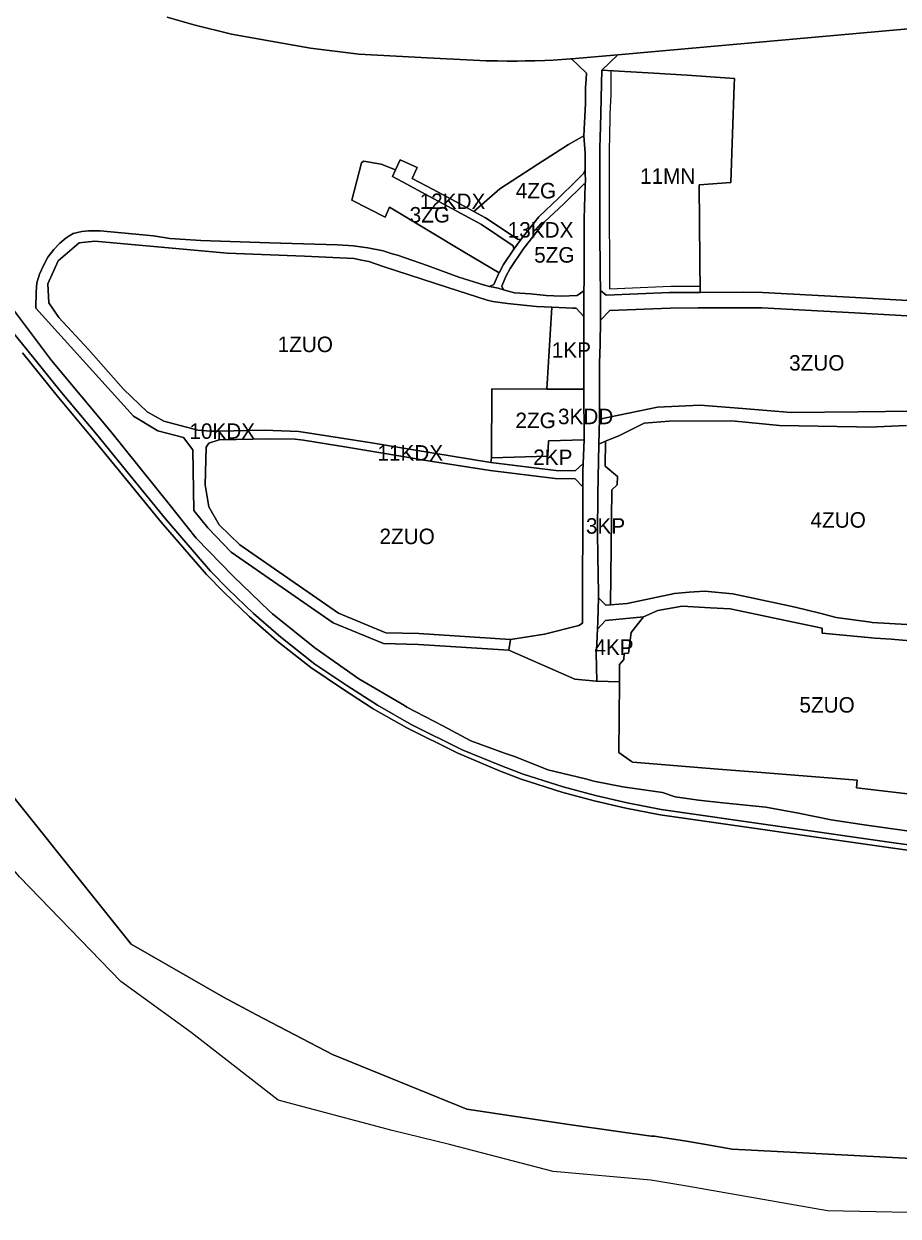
# Model space of a CAD drawing. Extents: x 7417411 to 7420955, y 5545251 to 5546537.
# Drawn here: x 7419574 to 7420138, y 5545252 to 5546021 of the extents above; entities that cross this region are included whole.
import ezdxf

# ---------------------------------------------------------------- set-up
doc = ezdxf.new("R2010")
doc.units = 0
for name, color, linetype in [('linie_rozgraniczajace', 7, 'Continuous'), ('linie_zabudowy_nieprzekraczalne', 7, 'Continuous'), ('oznaczenia_przeznaczen', 7, 'Continuous')]:
    doc.layers.add(name, color=color, linetype=linetype)

msp = doc.modelspace()

# ---------------------------------------------------------------- linework, layer by layer
at = {"layer": 'linie_rozgraniczajace'}
for points in [[(7419666.58, 5546025.71), (7419683.77, 5546020.6), (7419708.1, 5546014.69), (7419737.03, 5546009.53), (7419759.01, 5546005.6), (7419790.17, 5546001.84), (7419838.21, 5545999.23), (7419859.82, 5545998.12), (7419872.15, 5545997.57), (7419879.58, 5545997.4), (7419885.84, 5545997.33), (7419892.16, 5545997.32), (7419897.44, 5545997.4), (7419903.7, 5545997.53), (7419910.02, 5545997.76), (7419915.33, 5545998), (7419926.8, 5545998.72), (7419927.2, 5545998.75), (7419936.91, 5545989.53), (7419936.79, 5545985.72), (7419936.26, 5545979.98), (7419936.37, 5545970.02), (7419935.1, 5545949.12), (7419925.35, 5545943.45), (7419905.52, 5545930.91), (7419881.13, 5545914.93), (7419864.34, 5545900.22), (7419855.19, 5545905.19), (7419838.11, 5545914.37), (7419824.53, 5545921.65), (7419827.75, 5545928.74), (7419816.82, 5545933.69), (7419813.84, 5545927.12), (7419804.61, 5545930.73), (7419793.07, 5545932.68), (7419791.82, 5545931.67), (7419785.61, 5545907.57), (7419807.11, 5545896.72), (7419809.91, 5545903.04), (7419858.39, 5545873.92), (7419880.63, 5545860.7), (7419880.49, 5545860.43), (7419877.23, 5545853.15), (7419874.48, 5545851.98), (7419871.2, 5545852.8), (7419854.66, 5545857.97), (7419834.23, 5545865.36), (7419815.01, 5545872.14), (7419811.57, 5545872.89), (7419805.72, 5545874.8), (7419795.94, 5545876.75), (7419786.42, 5545878.09), (7419783.39, 5545878.32), (7419779.83, 5545878.59), (7419779.8, 5545878.59), (7419776.33, 5545878.67), (7419732.46, 5545880.14), (7419688.18, 5545881.56), (7419678.3, 5545882.15), (7419668.31, 5545882.92), (7419657.8, 5545884.64), (7419623.35, 5545887.75), (7419615.89, 5545887.87), (7419611.45, 5545887.4), (7419605.98, 5545886.05), (7419601.5, 5545883.34), (7419597.32, 5545879.85), (7419593.57, 5545875.79), (7419589.68, 5545870.81), (7419586.71, 5545865.38), (7419584.22, 5545859.91)], [(7420168.36, 5546020.35), (7419957.04, 5546001.38), (7419927.2, 5545998.75), (7419926.8, 5545998.72), (7419915.33, 5545998), (7419910.02, 5545997.76), (7419903.7, 5545997.53), (7419897.44, 5545997.4), (7419892.16, 5545997.32), (7419885.84, 5545997.33), (7419879.58, 5545997.4), (7419872.15, 5545997.57), (7419859.82, 5545998.12), (7419838.21, 5545999.23), (7419790.17, 5546001.84), (7419759.01, 5546005.6), (7419737.03, 5546009.53), (7419708.1, 5546014.69), (7419683.77, 5546020.6), (7419666.58, 5546025.71)], [(7420170.21, 5545841.46), (7420110.4, 5545844.83), (7420050.33, 5545848.06), (7420038.05, 5545848.19), (7420010.26, 5545848.07), (7420010.05, 5545868.95), (7420009.56, 5545917.41), (7420029.96, 5545919), (7420032.09, 5545981.78), (7420032.44, 5545986.18), (7420001.78, 5545988.13), (7419980.39, 5545989.43), (7419946.91, 5545991.52), (7419957.04, 5546001.38), (7420168.36, 5546020.35)], [(7420258.68, 5545252.15), (7420092.31, 5545255.64), (7420001.57, 5545271.49), (7419978.39, 5545275.32), (7419915.42, 5545281.02), (7419848.54, 5545298.42), (7419811.72, 5545307.45), (7419738.09, 5545326.91), (7419682.01, 5545370.56), (7419636.59, 5545403.58), (7419571.38, 5545471.15), (7419500.52, 5545553.16), (7419453.87, 5545603.37), (7419413.65, 5545646.88), (7419376.29, 5545683.4), (7419343.05, 5545716.25), (7419290.63, 5545776.17), (7419284.76, 5545784.57), (7419241.76, 5545833.26), (7419228.74, 5545841.09), (7419194.92, 5545858.79), (7419126.7, 5545886.6)], [(7420221.87, 5545481.1), (7420135.05, 5545493), (7419984.97, 5545514.41), (7419963.09, 5545518.7), (7419942.7, 5545523.52), (7419921.96, 5545529.13), (7419895.98, 5545537.26), (7419882.21, 5545542.72), (7419856.77, 5545552.95), (7419823.8, 5545569.35), (7419802.15, 5545581.76), (7419782.33, 5545594.48), (7419761.8, 5545608.35), (7419739.86, 5545625.61), (7419722.31, 5545640.96), (7419705.74, 5545656.93), (7419694.59, 5545668.32), (7419665.42, 5545702.07), (7419642.4, 5545730.26), (7419620.94, 5545756.55), (7419598.34, 5545783.6), (7419576.04, 5545811.27), (7419539.44, 5545856.07)], [(7419539.44, 5545856.07), (7419576.04, 5545811.27), (7419598.34, 5545783.6), (7419620.94, 5545756.55), (7419642.4, 5545730.26), (7419665.42, 5545702.07), (7419694.59, 5545668.32), (7419705.74, 5545656.93), (7419722.31, 5545640.96), (7419739.86, 5545625.61), (7419761.8, 5545608.35), (7419782.33, 5545594.48), (7419802.15, 5545581.76), (7419823.8, 5545569.35), (7419856.77, 5545552.95), (7419882.21, 5545542.72), (7419895.98, 5545537.26), (7419921.96, 5545529.13), (7419942.7, 5545523.52), (7419963.09, 5545518.7), (7419984.97, 5545514.41), (7420135.05, 5545493), (7420221.87, 5545481.1)], [(7419584.22, 5545859.91), (7419582.46, 5545854.21), (7419581.99, 5545848.36), (7419581.95, 5545837.84), (7419644.89, 5545768.14), (7419660.52, 5545758.68), (7419677.18, 5545754.39), (7419683.03, 5545746.6), (7419683.71, 5545707.48), (7419692.66, 5545696.13), (7419707.87, 5545680.56), (7419773.59, 5545634.93), (7419806.13, 5545621.55), (7419828.59, 5545621.01), (7419886.89, 5545617.18), (7419929.31, 5545598.57), (7419943.05, 5545597.24), (7419943.6, 5545597.22), (7419958.16, 5545596.85), (7419957.78, 5545551.25), (7419966.03, 5545545.48), (7419966.69, 5545545.02), (7420021.74, 5545540.53), (7420049.7, 5545538.31), (7420111.37, 5545533.38), (7420111.11, 5545528.55), (7420200.88, 5545517.97)], [(7420169.65, 5545831.47), (7420109.85, 5545834.85), (7420050.01, 5545838.06), (7420038.02, 5545838.19), (7420008.97, 5545838.06), (7419990.76, 5545837.98), (7419951.96, 5545836.4), (7419945.89, 5545830.16), (7419946.01, 5545839.64), (7419945.9, 5545849.36), (7419949.65, 5545846.32), (7419990.53, 5545847.98), (7420008.92, 5545848.06), (7420010.26, 5545848.07), (7420038.05, 5545848.19), (7420050.33, 5545848.06), (7420110.4, 5545844.83), (7420170.21, 5545841.46)], [(7420155.78, 5545499.11), (7420115.86, 5545504.53), (7420094.64, 5545507.9), (7420073.57, 5545512.14), (7420052.55, 5545516.03), (7420024.79, 5545518.7), (7420009.07, 5545520.48), (7419994.07, 5545522.71), (7419985.84, 5545525.56), (7419960.45, 5545529.08), (7419941.63, 5545532.71), (7419936.37, 5545534.17), (7419911.92, 5545540.05), (7419891.21, 5545548.51), (7419884.14, 5545550.77), (7419862.36, 5545558.84), (7419844.27, 5545568.42), (7419821.09, 5545580.55), (7419819.5, 5545581.6), (7419790.12, 5545598.73), (7419761.76, 5545618.85), (7419734.55, 5545640.69), (7419732.24, 5545642.7), (7419709.32, 5545664.77), (7419685.14, 5545689.52), (7419667.86, 5545711.44), (7419630.05, 5545758.49), (7419591.92, 5545804.1), (7419564.22, 5545841.04)], [(7419564.22, 5545841.04), (7419591.92, 5545804.1), (7419630.05, 5545758.49), (7419667.86, 5545711.44), (7419685.14, 5545689.52), (7419709.32, 5545664.77), (7419732.24, 5545642.7), (7419734.55, 5545640.69), (7419761.76, 5545618.85), (7419790.12, 5545598.73), (7419819.5, 5545581.6), (7419821.09, 5545580.55), (7419844.27, 5545568.42), (7419862.36, 5545558.84), (7419884.14, 5545550.77), (7419891.21, 5545548.51), (7419911.92, 5545540.05), (7419936.37, 5545534.17), (7419941.63, 5545532.71), (7419960.45, 5545529.08), (7419985.84, 5545525.56), (7419994.07, 5545522.71), (7420009.07, 5545520.48), (7420024.79, 5545518.7), (7420052.55, 5545516.03), (7420073.57, 5545512.14), (7420094.64, 5545507.9), (7420115.86, 5545504.53), (7420155.78, 5545499.11)], [(7420147.34, 5545771.5), (7420112.06, 5545771.08), (7420068.85, 5545770.57), (7420037.46, 5545773.21), (7420010.13, 5545775.34), (7419982.63, 5545774), (7419945.21, 5545766.35), (7419945.35, 5545776.95), (7419945.4, 5545802.63), (7419945.69, 5545814.38), (7419945.89, 5545830.16), (7419951.96, 5545836.4), (7419990.76, 5545837.98), (7420008.97, 5545838.06), (7420038.02, 5545838.19), (7420050.01, 5545838.06), (7420109.85, 5545834.85), (7420169.65, 5545831.47)], [(7419573.33, 5545809.06), (7419595.63, 5545781.39), (7419618.23, 5545754.34), (7419639.69, 5545728.05), (7419662.71, 5545699.86), (7419691.88, 5545666.11), (7419703.03, 5545654.71), (7419719.6, 5545638.74), (7419737.15, 5545623.39), (7419759.09, 5545606.14), (7419779.62, 5545592.26), (7419799.44, 5545579.54), (7419821.09, 5545567.13), (7419854.06, 5545550.73), (7419880.92, 5545539.46), (7419894.81, 5545533.96), (7419920.98, 5545525.77), (7419941.84, 5545520.13), (7419962.35, 5545515.28), (7419984.39, 5545510.96), (7420134.57, 5545489.53), (7420221.39, 5545477.63)], [(7420221.39, 5545477.63), (7420134.57, 5545489.53), (7419984.39, 5545510.96), (7419962.35, 5545515.28), (7419941.84, 5545520.13), (7419920.98, 5545525.77), (7419894.81, 5545533.96), (7419880.92, 5545539.46), (7419854.06, 5545550.73), (7419821.09, 5545567.13), (7419799.44, 5545579.54), (7419779.62, 5545592.26), (7419759.09, 5545606.14), (7419737.15, 5545623.39), (7419719.6, 5545638.74), (7419703.03, 5545654.71), (7419691.88, 5545666.11), (7419662.71, 5545699.86), (7419639.69, 5545728.05), (7419618.23, 5545754.34), (7419595.63, 5545781.39), (7419573.33, 5545809.06)], [(7420143.31, 5545762.32), (7420119.12, 5545761.17), (7420111.09, 5545761.33), (7420061.26, 5545762.26), (7420030.56, 5545765.15), (7419990.14, 5545765.11), (7419974.08, 5545763.67), (7419958.15, 5545755.85), (7419949.12, 5545752.01), (7419944.97, 5545750.25), (7419945.21, 5545766.35), (7419982.63, 5545774), (7420010.13, 5545775.34), (7420037.46, 5545773.21), (7420068.85, 5545770.57), (7420112.06, 5545771.08), (7420147.34, 5545771.5)], [(7420143.47, 5545633.81), (7420121.13, 5545635.19), (7420120.27, 5545635.24), (7420097.93, 5545638.44), (7420087.33, 5545641.07), (7420071.39, 5545645.03), (7420063.48, 5545646.75), (7420031.23, 5545653.68), (7420013, 5545655.38), (7420003.06, 5545654.63), (7419993.71, 5545653.93), (7419963.08, 5545647.49), (7419952.44, 5545646.62), (7419953.27, 5545720.72), (7419956.7, 5545724.02), (7419956.87, 5545729.28), (7419948.86, 5545736.06), (7419949.12, 5545752.01), (7419958.15, 5545755.85), (7419974.08, 5545763.67), (7419990.14, 5545765.11), (7420030.56, 5545765.15), (7420061.26, 5545762.26), (7420111.09, 5545761.33), (7420119.12, 5545761.17), (7420143.31, 5545762.32)], [(7420177.52, 5545620.45), (7420133.26, 5545624.46), (7420123.12, 5545624.99), (7420088.86, 5545628.15), (7420088.77, 5545631.5), (7420065.26, 5545636.42), (7420034.69, 5545642.83), (7420029.6, 5545643.89), (7420016.81, 5545644.6), (7420006, 5545645.2), (7419998.55, 5545645.61), (7419982.91, 5545642.83), (7419973.68, 5545638.72), (7419949.24, 5545636.39), (7419944.01, 5545630.93), (7419944.26, 5545635.91), (7419944.58, 5545650.98), (7419949.49, 5545646.39), (7419952.44, 5545646.62), (7419963.08, 5545647.49), (7419993.71, 5545653.93), (7420003.06, 5545654.63), (7420013, 5545655.38), (7420031.23, 5545653.68), (7420063.48, 5545646.75), (7420071.39, 5545645.03), (7420087.33, 5545641.07), (7420097.93, 5545638.44), (7420120.27, 5545635.24), (7420121.13, 5545635.19), (7420143.47, 5545633.81)], [(7420200.88, 5545517.97), (7420111.11, 5545528.55), (7420111.37, 5545533.38), (7420049.7, 5545538.31), (7420021.74, 5545540.53), (7419966.69, 5545545.02), (7419966.03, 5545545.48), (7419957.78, 5545551.25), (7419958.16, 5545596.85), (7419958.25, 5545607.99), (7419960.94, 5545611.36), (7419961.17, 5545615.23), (7419963.92, 5545615.35), (7419965.7, 5545628.78), (7419973.68, 5545638.72), (7419982.91, 5545642.83), (7419998.55, 5545645.61), (7420006, 5545645.2), (7420016.81, 5545644.6), (7420029.6, 5545643.89), (7420034.69, 5545642.83), (7420065.26, 5545636.42), (7420088.77, 5545631.5), (7420088.86, 5545628.15), (7420123.12, 5545624.99), (7420133.26, 5545624.46), (7420177.52, 5545620.45)], [(7419538.5, 5545558.64), (7419643.4, 5545427.59), (7419702.88, 5545393.38), (7419724.2, 5545382.02), (7419773.24, 5545356.42), (7419859.86, 5545321.2), (7419925.47, 5545311.24), (7419955.86, 5545306.93), (7419978.62, 5545303.7), (7419980.72, 5545303.76), (7419984.66, 5545303.08), (7419994.42, 5545301.67), (7420001.49, 5545300.57), (7420013.86, 5545298.41), (7420030.92, 5545295.44), (7420105.46, 5545291.6), (7420195.89, 5545286.82)], [(7420195.89, 5545286.82), (7420105.46, 5545291.6), (7420030.92, 5545295.44), (7420013.86, 5545298.41), (7420001.49, 5545300.57), (7419994.42, 5545301.67), (7419984.66, 5545303.08), (7419980.72, 5545303.76), (7419978.62, 5545303.7), (7419955.86, 5545306.93), (7419925.47, 5545311.24), (7419859.86, 5545321.2), (7419773.24, 5545356.42), (7419724.2, 5545382.02), (7419702.88, 5545393.38), (7419643.4, 5545427.59), (7419538.5, 5545558.64)]]:
    msp.add_lwpolyline(points, dxfattribs=at)
for points in [[(7419886.89, 5545617.18), (7419887.94, 5545624.12), (7419909.77, 5545627.62), (7419932.08, 5545633.13), (7419934.25, 5545634.77), (7419934.55, 5545722.65), (7419934.57, 5545727.64), (7419934.66, 5545732.8), (7419934.84, 5545737.8), (7419935.38, 5545752.92), (7419935.4, 5545753.62), (7419935.3, 5545785.56), (7419935.18, 5545832.57), (7419935.17, 5545837.55), (7419935.14, 5545849.17), (7419935.35, 5545855.31), (7419935.36, 5545861.5), (7419935.35, 5545869.11), (7419935.34, 5545895.47), (7419936.16, 5545917.56), (7419936.26, 5545920.25), (7419936.16, 5545925.11), (7419936.13, 5545927.16), (7419935.97, 5545937.91), (7419935.1, 5545949.12), (7419936.37, 5545970.02), (7419936.26, 5545979.98), (7419936.79, 5545985.72), (7419936.91, 5545989.53), (7419927.2, 5545998.75), (7419957.04, 5546001.38), (7419946.91, 5545991.52), (7419946.46, 5545973.54), (7419946.06, 5545963.03), (7419945.78, 5545947.73), (7419945.59, 5545941.76), (7419945.59, 5545914.41), (7419945.54, 5545888.51), (7419945.72, 5545861.23), (7419945.9, 5545849.36), (7419946.01, 5545839.64), (7419945.89, 5545830.16), (7419945.69, 5545814.38), (7419945.4, 5545802.63), (7419945.35, 5545776.95), (7419945.21, 5545766.35), (7419944.97, 5545750.25), (7419944.25, 5545717.73), (7419943.96, 5545692.69), (7419944.33, 5545678.08), (7419944.62, 5545653.83), (7419944.58, 5545650.98), (7419944.26, 5545635.91), (7419944.01, 5545630.93), (7419943.78, 5545626.45), (7419943.48, 5545620.76), (7419943.18, 5545615.27), (7419943.6, 5545597.22), (7419943.05, 5545597.24), (7419929.31, 5545598.57)], [(7419945.9, 5545849.36), (7419945.72, 5545861.23), (7419945.54, 5545888.51), (7419945.59, 5545914.41), (7419945.59, 5545941.76), (7419945.78, 5545947.73), (7419946.06, 5545963.03), (7419946.46, 5545973.54), (7419946.91, 5545991.52), (7419980.39, 5545989.43), (7420001.78, 5545988.13), (7420032.44, 5545986.18), (7420032.09, 5545981.78), (7420029.96, 5545919), (7420009.56, 5545917.41), (7420010.05, 5545868.95), (7420010.26, 5545848.07), (7420008.92, 5545848.06), (7419990.53, 5545847.98), (7419949.65, 5545846.32)], [(7419864.34, 5545900.22), (7419881.13, 5545914.93), (7419905.52, 5545930.91), (7419925.35, 5545943.45), (7419935.1, 5545949.12), (7419935.97, 5545937.91), (7419936.13, 5545927.16), (7419935.12, 5545924.91), (7419930.23, 5545920.08), (7419918.87, 5545908.85), (7419906.14, 5545896.93), (7419894.82, 5545882.46), (7419892.84, 5545882.16), (7419871.73, 5545896.2)], [(7419785.61, 5545907.57), (7419791.82, 5545931.67), (7419793.07, 5545932.68), (7419804.61, 5545930.73), (7419813.84, 5545927.12), (7419811.86, 5545922.77), (7419817.84, 5545919.63), (7419818.25, 5545919.34), (7419835.74, 5545909.97), (7419852.81, 5545900.79), (7419869.15, 5545891.92), (7419889.73, 5545878.23), (7419890.1, 5545876.02), (7419883.35, 5545866.03), (7419880.63, 5545860.7), (7419858.39, 5545873.92), (7419809.91, 5545903.04), (7419807.11, 5545896.72)], [(7419811.86, 5545922.77), (7419813.84, 5545927.12), (7419816.82, 5545933.69), (7419827.75, 5545928.74), (7419824.53, 5545921.65), (7419838.11, 5545914.37), (7419855.19, 5545905.19), (7419864.34, 5545900.22), (7419871.73, 5545896.2), (7419892.84, 5545882.16), (7419894.82, 5545882.46), (7419890.1, 5545876.02), (7419889.73, 5545878.23), (7419869.15, 5545891.92), (7419852.81, 5545900.79), (7419835.74, 5545909.97), (7419818.25, 5545919.34), (7419817.84, 5545919.63)], [(7419874.48, 5545851.98), (7419877.23, 5545853.15), (7419880.49, 5545860.43), (7419880.63, 5545860.7), (7419883.35, 5545866.03), (7419890.1, 5545876.02), (7419894.82, 5545882.46), (7419906.14, 5545896.93), (7419918.87, 5545908.85), (7419930.23, 5545920.08), (7419935.12, 5545924.91), (7419936.13, 5545927.16), (7419936.16, 5545925.11), (7419936.26, 5545920.25), (7419936.16, 5545917.56), (7419935.21, 5545917.98), (7419922.33, 5545905.25), (7419909.84, 5545893.55), (7419896.16, 5545876.06), (7419887.66, 5545863.49), (7419885, 5545858.27), (7419882.26, 5545852.15), (7419883.45, 5545849.82), (7419879.99, 5545850.85), (7419877.76, 5545851.16)], [(7419882.26, 5545852.15), (7419885, 5545858.27), (7419887.66, 5545863.49), (7419896.16, 5545876.06), (7419909.84, 5545893.55), (7419922.33, 5545905.25), (7419935.21, 5545917.98), (7419936.16, 5545917.56), (7419935.34, 5545895.47), (7419935.35, 5545869.11), (7419935.36, 5545861.5), (7419935.35, 5545855.31), (7419935.14, 5545849.17), (7419930.87, 5545846.09), (7419920.87, 5545845.59), (7419910.81, 5545846.01), (7419900.82, 5545847.08), (7419890.56, 5545847.72), (7419883.45, 5545849.82)], [(7419581.95, 5545837.84), (7419581.99, 5545848.36), (7419582.46, 5545854.21), (7419584.22, 5545859.91), (7419586.71, 5545865.38), (7419589.68, 5545870.81), (7419593.57, 5545875.79), (7419597.32, 5545879.85), (7419601.5, 5545883.34), (7419605.98, 5545886.05), (7419611.45, 5545887.4), (7419615.89, 5545887.87), (7419623.35, 5545887.75), (7419657.8, 5545884.64), (7419668.31, 5545882.92), (7419678.3, 5545882.15), (7419688.18, 5545881.56), (7419732.46, 5545880.14), (7419776.33, 5545878.67), (7419779.8, 5545878.59), (7419779.83, 5545878.59), (7419783.39, 5545878.32), (7419786.42, 5545878.09), (7419795.94, 5545876.75), (7419805.72, 5545874.8), (7419811.57, 5545872.89), (7419815.01, 5545872.14), (7419834.23, 5545865.36), (7419854.66, 5545857.97), (7419871.2, 5545852.8), (7419874.48, 5545851.98), (7419877.76, 5545851.16), (7419879.99, 5545850.85), (7419883.45, 5545849.82), (7419890.56, 5545847.72), (7419900.82, 5545847.08), (7419910.81, 5545846.01), (7419920.87, 5545845.59), (7419930.87, 5545846.09), (7419935.14, 5545849.17), (7419935.17, 5545837.55), (7419935.18, 5545832.57), (7419930.17, 5545837.82), (7419928, 5545837.94), (7419914.62, 5545838.51), (7419904.78, 5545838.93), (7419885.88, 5545840.98), (7419876.62, 5545842.28), (7419872.88, 5545843.07), (7419847.52, 5545851.27), (7419805.84, 5545864.88), (7419796.62, 5545867.92), (7419791.89, 5545868.9), (7419787.06, 5545869.9), (7419755.2, 5545871.48), (7419705.3, 5545873.34), (7419686.23, 5545875.04), (7419619.86, 5545881.04), (7419609.72, 5545880.02), (7419596.3, 5545868.55), (7419589.56, 5545853.7), (7419590.23, 5545841.38), (7419596.74, 5545831.91), (7419615.87, 5545811.34), (7419638.48, 5545785.68), (7419653.59, 5545770.98), (7419664.36, 5545764.91), (7419686.25, 5545759.28), (7419694.63, 5545758.51), (7419700.05, 5545758.6), (7419700.15, 5545753), (7419693.32, 5545750.84), (7419691.75, 5545748.23), (7419691.02, 5545723.97), (7419693.35, 5545709.84), (7419700.12, 5545698.17), (7419713.49, 5545685.18), (7419776.96, 5545641.11), (7419807.6, 5545628.52), (7419828.9, 5545628), (7419887.94, 5545624.12), (7419886.89, 5545617.18), (7419828.59, 5545621.01), (7419806.13, 5545621.55), (7419773.59, 5545634.93), (7419707.87, 5545680.56), (7419692.66, 5545696.13), (7419683.71, 5545707.48), (7419683.03, 5545746.6), (7419677.18, 5545754.39), (7419660.52, 5545758.68), (7419644.89, 5545768.14)], [(7419589.56, 5545853.7), (7419596.3, 5545868.55), (7419609.72, 5545880.02), (7419619.86, 5545881.04), (7419686.23, 5545875.04), (7419705.3, 5545873.34), (7419755.2, 5545871.48), (7419787.06, 5545869.9), (7419791.89, 5545868.9), (7419796.62, 5545867.92), (7419805.84, 5545864.88), (7419847.52, 5545851.27), (7419872.88, 5545843.07), (7419876.62, 5545842.28), (7419885.88, 5545840.98), (7419904.78, 5545838.93), (7419914.62, 5545838.51), (7419911.45, 5545785.66), (7419875.87, 5545785.81), (7419875.7, 5545741.28), (7419875.27, 5545738.41), (7419825.45, 5545746.58), (7419797.11, 5545751.24), (7419751.5, 5545758.45), (7419729.17, 5545759.13), (7419700.05, 5545758.6), (7419694.63, 5545758.51), (7419686.25, 5545759.28), (7419664.36, 5545764.91), (7419653.59, 5545770.98), (7419638.48, 5545785.68), (7419615.87, 5545811.34), (7419596.74, 5545831.91), (7419590.23, 5545841.38)], [(7419911.45, 5545785.66), (7419914.62, 5545838.51), (7419928, 5545837.94), (7419930.17, 5545837.82), (7419935.18, 5545832.57), (7419935.3, 5545785.56)], [(7419875.7, 5545741.28), (7419875.87, 5545785.81), (7419911.45, 5545785.66), (7419935.3, 5545785.56), (7419935.4, 5545753.62), (7419935.38, 5545752.92), (7419912.51, 5545752.36), (7419912.01, 5545742.48)], [(7419700.15, 5545753), (7419700.05, 5545758.6), (7419729.17, 5545759.13), (7419751.5, 5545758.45), (7419797.11, 5545751.24), (7419825.45, 5545746.58), (7419875.27, 5545738.41), (7419917.05, 5545733.2), (7419929.66, 5545732.91), (7419934.84, 5545737.8), (7419934.66, 5545732.8), (7419934.57, 5545727.64), (7419934.55, 5545722.65), (7419929.57, 5545727.76), (7419916.75, 5545728.05), (7419874.73, 5545733.29), (7419830.75, 5545740.08), (7419824.95, 5545741.06), (7419782.41, 5545748.19), (7419754.38, 5545752.68), (7419749.01, 5545753.3), (7419732.69, 5545753.55)], [(7419691.02, 5545723.97), (7419691.75, 5545748.23), (7419693.32, 5545750.84), (7419700.15, 5545753), (7419732.69, 5545753.55), (7419749.01, 5545753.3), (7419754.38, 5545752.68), (7419782.41, 5545748.19), (7419824.95, 5545741.06), (7419830.75, 5545740.08), (7419874.73, 5545733.29), (7419916.75, 5545728.05), (7419929.57, 5545727.76), (7419934.55, 5545722.65), (7419934.25, 5545634.77), (7419932.08, 5545633.13), (7419909.77, 5545627.62), (7419887.94, 5545624.12), (7419828.9, 5545628), (7419807.6, 5545628.52), (7419776.96, 5545641.11), (7419713.49, 5545685.18), (7419700.12, 5545698.17), (7419693.35, 5545709.84)], [(7419875.27, 5545738.41), (7419875.7, 5545741.28), (7419912.01, 5545742.48), (7419912.51, 5545752.36), (7419935.38, 5545752.92), (7419934.84, 5545737.8), (7419929.66, 5545732.91), (7419917.05, 5545733.2)], [(7419944.58, 5545650.98), (7419944.62, 5545653.83), (7419944.33, 5545678.08), (7419943.96, 5545692.69), (7419944.25, 5545717.73), (7419944.97, 5545750.25), (7419949.12, 5545752.01), (7419948.86, 5545736.06), (7419956.87, 5545729.28), (7419956.7, 5545724.02), (7419953.27, 5545720.72), (7419952.44, 5545646.62), (7419949.49, 5545646.39)], [(7419943.6, 5545597.22), (7419943.18, 5545615.27), (7419943.48, 5545620.76), (7419943.78, 5545626.45), (7419944.01, 5545630.93), (7419949.24, 5545636.39), (7419973.68, 5545638.72), (7419965.7, 5545628.78), (7419963.92, 5545615.35), (7419961.17, 5545615.23), (7419960.94, 5545611.36), (7419958.25, 5545607.99), (7419958.16, 5545596.85)]]:
    msp.add_lwpolyline(points, close=True, dxfattribs=at)
at = {"layer": 'linie_zabudowy_nieprzekraczalne'}
for points in [[(7419952.69, 5545991.15), (7419952.52, 5545975.92), (7419952.06, 5545962.87), (7419951.78, 5545947.58), (7419951.59, 5545941.66), (7419951.59, 5545914.42), (7419951.7, 5545850.4)], [(7419951.7, 5545850.4), (7419991.32, 5545852.01), (7420010.22, 5545852.1)]]:
    msp.add_lwpolyline(points, dxfattribs=at)

# ---------------------------------------------------------------- texts
at = {"layer": 'oznaczenia_przeznaczen'}
for s, p in [('11MN', (7419971.45, 5545918.12)), ('4ZG', (7419891.31, 5545908.73)), ('12KDX', (7419829.34, 5545901.87)), ('3ZG', (7419822.9, 5545893.16)), ('13KDX', (7419886.11, 5545883.44)), ('5ZG', (7419903.19, 5545867.28)), ('1ZUO', (7419737.77, 5545809.56)), ('1KP', (7419914.53, 5545805.91)), ('3ZUO', (7420067.55, 5545797.65)), ('2ZG', (7419891.11, 5545760.5)), ('3KDD', (7419918.52, 5545763.06)), ('10KDX', (7419680.86, 5545753.59)), ('11KDX', (7419802.1, 5545739.54)), ('2KP', (7419902.57, 5545736.73)), ('3KP', (7419936.56, 5545692.43)), ('4ZUO', (7420081.38, 5545696.3)), ('2ZUO', (7419803.44, 5545685.69)), ('4KP', (7419942.02, 5545614.21)), ('5ZUO', (7420074.19, 5545576.99))]:
    msp.add_text(s, height=10, dxfattribs=at).set_placement(p)

doc.saveas('drawing.dxf')
